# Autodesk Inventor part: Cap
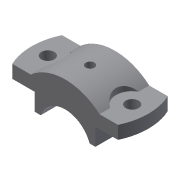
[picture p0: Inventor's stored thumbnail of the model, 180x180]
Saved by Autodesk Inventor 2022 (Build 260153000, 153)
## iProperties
Created: 2002-02
Part Number: Cap
Document SubType Name: Modeling
Designer: ***
Density: 1 g/cm^3
Material: Generic
Appearance: Default
Control State: 0
Master: False
Checked Out: False
Shininess: 77.0
Angle Display Precision: 2
Document Length Units: 11269
Document Angle Units: 11279
Document Time Units: 11290
Document Mass Units: 11283
Document Length Units Precision: 3
Document Angle Units Precision: 2
Density: 0.0
Volumn: 0.0
Area: 0.0
PropertySet Name: Model Information
Author: ***
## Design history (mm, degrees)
sketch "Sketch2"
  geometry: L1 (22.656, 22.99)-(28.029, 22.99); L2 (28.029, 22.99)-(28.029, 38.99); L3 (28.029, 38.99)-(54.029, 38.99); L4 (54.029, 38.99)-(54.029, 50.99); L5 (54.029, 50.99)-(31.778, 50.99); L6 (-22.599, 22.99)-(-27.971, 22.99); L7 (-27.971, 22.99)-(-27.971, 38.99); L8 (-27.971, 38.99)-(-53.971, 38.99); L9 (-53.971, 38.99)-(-53.971, 50.99); L10 (-53.971, 50.99)-(-31.72, 50.99); A1 r 24 centre (0.029, 14.99) between (22.656, 22.99) and (-22.599, 22.99); A2 r 48 centre (0.029, 14.99) between (31.778, 50.99) and (-31.72, 50.99)
  constraints: 20 end point, 5 equal length, 4 parallel, 4 perpendicular, 4 point on circle, 2 centre point, 1 coincident, 1 horizontal, 1 point on line
  dimensions: "d0" = 24 radius of A1; "d1" = 8 distance from line of L1 A1.centre; "d2" = 12 distance of L8.end L9.end; "d3" = 16 distance of L6.end L7.end; "d4" = 48 radius of A2; "d5" = 108 distance between parallel lines of L9 L4; "d6" = 56 distance between parallel lines of L7 L2
extrude "Extrusion1" new body sketch "Sketch2" stored distance "d7" = 46; taper "d8" = 0 deg
sketch "Sketch3"
  geometry: L1 (17.108, 0)-(40.349, 0); L2 (40.349, 0)-(40.349, -46); L3 (40.349, -46)-(17.108, -46); L4 (0, -46)-(22.251, -46) reference; L5 (22.251, 0)-(0, 0) reference; L6 (22.251, 0)-(22.251, -46) reference; A1 r 54 centre (-31.749, -23) between (17.108, -46) and (17.108, 0)
  constraints: 6 end point, 2 collinear, 2 point on circle, 1 centre point, 1 horizontal, 1 parallel, 1 perpendicular, 1 vertical alignment
  dimensions: "d9" = 54 radius of A1; "d10" = 54 distance from line of L6 A1.centre
extrude "Extrusion2" cut sketch "Sketch3" extent not by distance; stored distance "d11" = 46; taper "d12" = 0 deg
sketch "Sketch4"
  geometry: L1 (17.108, 46)-(0, 46) reference; A1 r 54 centre (-31.749, 23) between (17.108, 0) and (17.108, 46) reference; 1 further point
  dimensions: "d13" = 23 distance from line of L1 point (7.251, 23); "d14" = 39 distance of A1.centre point (7.251, 23)
hole "Hole1" sketch "Sketch4" diameter "d15" = 30; stored, may be unused: countersink angle "d19" = 82 deg, drill point angle "d21" = 118 deg; dims "d16" = 6, "d17" = 4, "d18" = 2, "d20" = 8
hole "Hole2" sketch "Sketch4" diameter "d22" = 12; stored, may be unused: countersink angle "d26" = 82 deg, drill point angle "d28" = 118 deg; dims "d23" = 6, "d24" = 4, "d25" = 2, "d27" = 8
workplane "Work Plane1"
mirror "Mirror1"
workplane "Work Plane2"
sketch "Sketch5"
  geometry: L1 (31.749, -23)-(-31.749, -23) reference; C1 r 6 at (39, 0) reference; 1 further point
  dimensions: "d30" = 23 distance from line of L1 point (0, 0); "d31" = 39 distance of C1.centre point (0, 0)
hole "Hole3" sketch "Sketch5" at (0, 0) diameter "d32" = 6; stored, may be unused: countersink angle "d36" = 82 deg, drill point angle "d38" = 118 deg; dims "d33" = 6, "d34" = 8, "d35" = 16, "d37" = 8
body "Solid1"
other parameters: "d29" = -54
